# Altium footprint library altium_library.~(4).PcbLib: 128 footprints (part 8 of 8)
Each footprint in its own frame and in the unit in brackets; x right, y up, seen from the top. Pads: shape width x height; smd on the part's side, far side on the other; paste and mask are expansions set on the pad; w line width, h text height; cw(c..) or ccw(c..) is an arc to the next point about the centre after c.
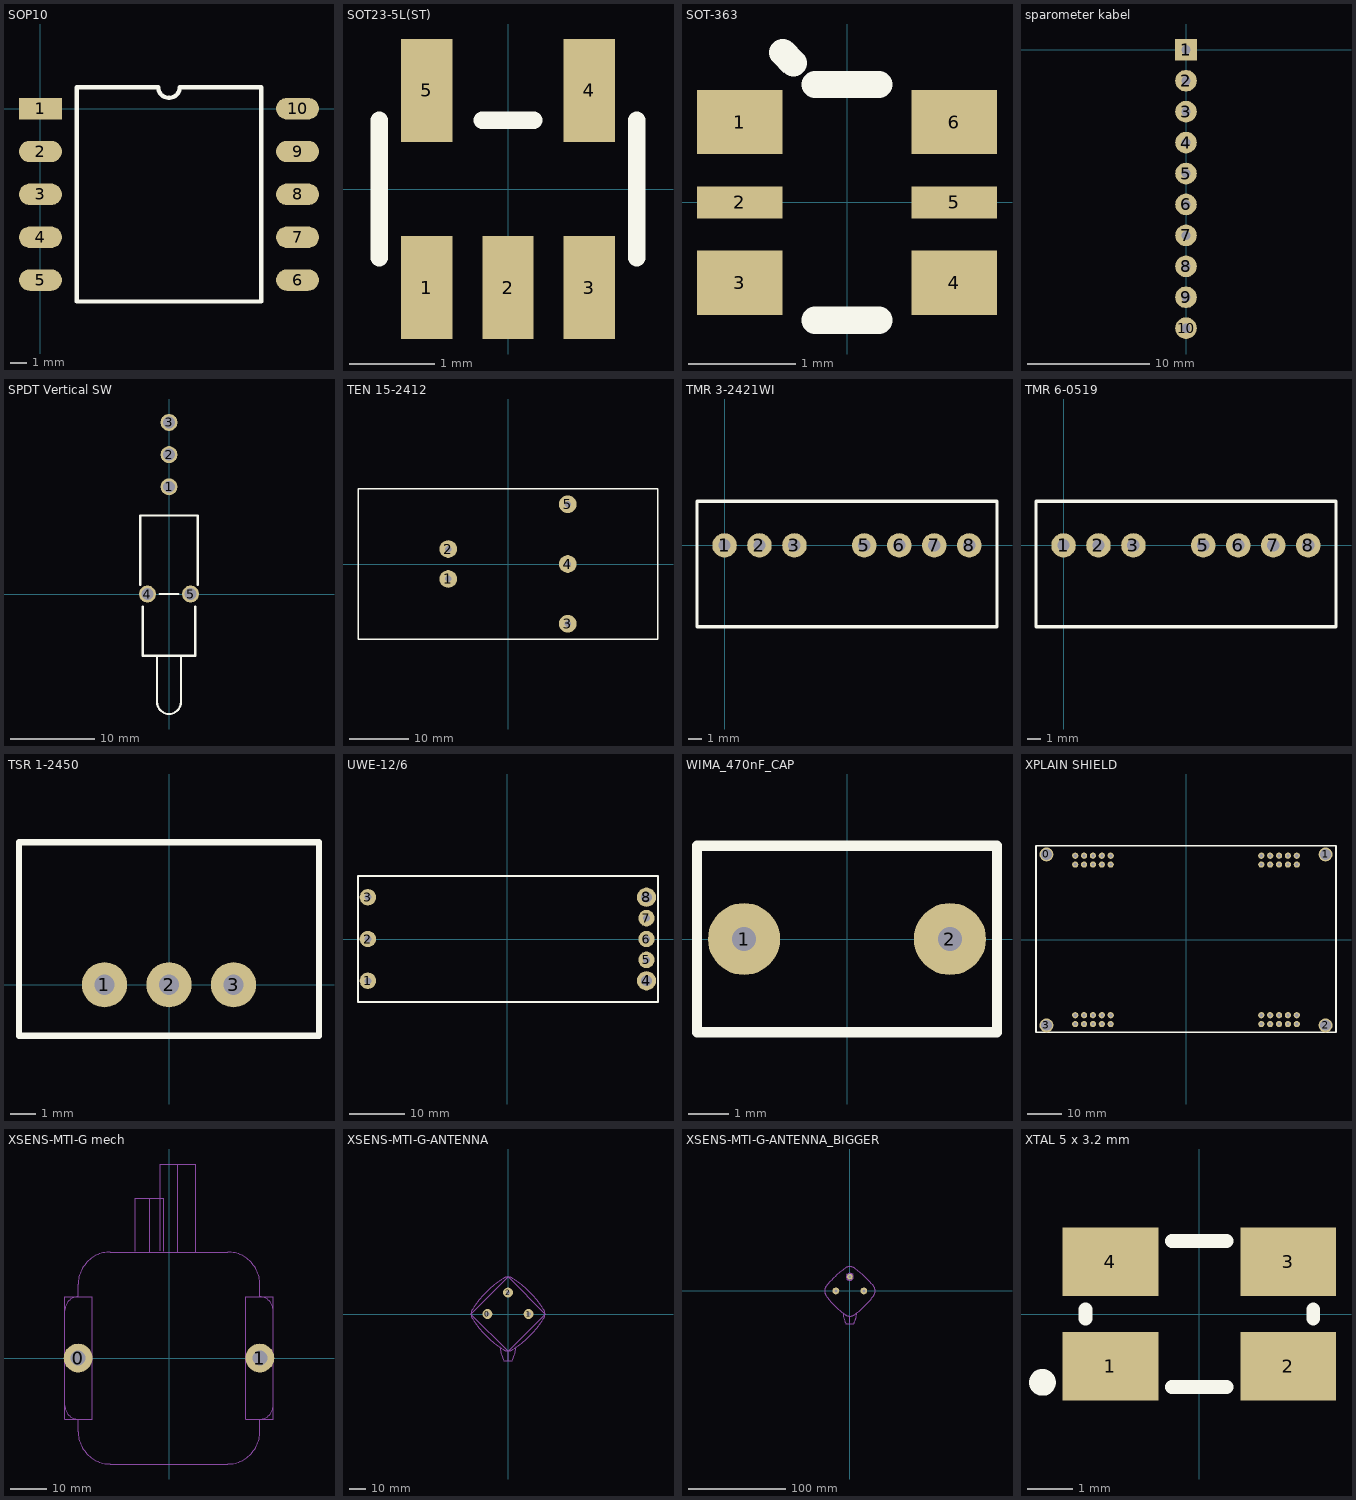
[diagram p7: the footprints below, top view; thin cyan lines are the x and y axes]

## SOP10 [mil]
pads (10):
  rect 100x50 smd: 1(0,0)
  oval 100x50 smd: 2(0,-100) 3(0,-200) 4(0,-300) 5(0,-400) 6(600,-400) 7(600,-300) 8(600,-200) 9(600,-100) 10(600,0)
Top Overlay:
  lines w10: 85,-450 515,-450 515,50 325,50 cw(c300,50) 275,50 85,50 85,-450

## SOT23-5L(ST) [mm]
pads (5):
  rect 0.6x1.2 smd: 1(-0.95,-1.15) 2(0,-1.15) 3(0.95,-1.15) 4(0.95,1.15) 5(-0.95,1.15)
Top Overlay:
  lines w0.203: -1.5,-0.8 -1.5,0.8 ; -0.3,0.8 0.3,0.8 ; 1.5,-0.8 1.5,0.8

## SOT-363 [mm]
pads (6):
  rect 0.8x0.6 smd: 1(-1,0.75) 3(-1,-0.75) 4(1,-0.75) 6(1,0.75)
  rect 0.8x0.3 smd: 2(-1,0) 5(1,0)
Top Overlay:
  lines w0.254: -0.6,1.4 -0.5,1.3 ; -0.3,-1.1 0.3,-1.1 ; -0.3,1.1 0.3,1.1

## sparometer kabel [mil]
pads (10):
  rect 70x70 hole 30: 1(0,0)
  round 70 hole 30: 2(0,-100) 3(0,-200) 4(0,-300) 5(0,-400) 6(0,-500) 7(0,-600) 8(0,-700) 9(0,-800) 10(0,-900)

## SPDT Vertical SW [mm] "T80-T Salecom"
pads (5):
  round 2 hole 1.4: 1(0,12.7) 2(0,16.51) 3(0,20.32) 4(-2.55,0) 5(2.55,0)
Top Overlay:
  lines w0.254: -3.4,1.1 -3.4,9.3 3.4,9.3 3.4,1.1 ; -3.1,-1.5 -3.1,-7.3 3.1,-7.3 3.1,-1.5 ; -1.4,-7.3 -1.4,-12.8 ccw(c0,-12.8) 1.4,-12.8 1.4,-7.3 ; -1.1,0 1.1,0

## TEN 15-2412 [mm]
pads (5):
  round 3 hole 1.1: 1(-10.16,-2.54) 2(-10.16,2.54) 3(10.16,-10.16) 4(10.16,0) 5(10.16,10.16)
Top Overlay:
  lines w0.254: 19.5,12.8 25.5,12.8 25.5,-12.8 -25.5,-12.8 -25.5,12.8 1.2,12.8 20.6,12.8

## TMR 3-2421WI [mil] "+-5v DC-DC converter 3W"
pads (7):
  round 70 hole 35.43: 1(0,0) 2(100,0) 3(200,0) 5(400,0) 6(500,0) 7(600,0) 8(700,0)
Top Overlay:
  lines w10: -78.74,-232.28 -78.74,125.98 779.53,125.98 779.53,-232.28 -78.74,-232.28

## TMR 6-0519 [mil] "9V DC-DC converter 6W"
pads (7):
  round 70 hole 35.43: 1(0,0) 2(100,0) 3(200,0) 5(400,0) 6(500,0) 7(600,0) 8(700,0)
Top Overlay:
  lines w10: -78.74,-232.28 -78.74,125.98 779.53,125.98 779.53,-232.28 -78.74,-232.28

## TSR 1-2450 [mil] "5V regulator"
pads (3):
  round 70 hole 31.5: 1(-100,0) 2(0,0) 3(100,0)
Top Overlay:
  lines w10: -232.28,-78.74 -232.28,220.47 232.28,220.47 232.28,-78.74 -232.28,-78.74

## UWE-12/6 [mm] "12 til 12 V 6A DC DC converter"
pads (8):
  round 3 hole 1.27: 1(-25.4,-7.62) 2(-25.4,0) 3(-25.4,7.62) 5(25.4,-3.81) 6(25.4,0) 7(25.4,3.81)
  round 3.5 hole 1.93: 4(25.4,-7.62) 8(25.4,7.62)
Top Overlay:
  lines w0.305: -27.2,-11.5 -27.2,11.5 27.5,11.5 27.5,-11.5 -27.2,-11.5

## WIMA_470nF_CAP [mil]
pads (2):
  round 70 hole 23.62: 1(-100,0) 2(100,0)
Top Overlay:
  lines w10: -145.67,-90.55 145.67,-90.55 145.67,90.55 -145.67,90.55 -145.67,-90.55

## XPLAIN SHIELD [mil]
pads (44):
  round 157.48 hole 122.05: 0(-1574.8,964.57) 1(1574.8,964.57) 2(1574.8,-964.57) 3(-1574.8,-964.57)
  round 70 hole 35.43: 11(850,850) 12(850,950) 13(950,850) 14(950,950) 15(1050,850) 16(1050,950) 17(1150,850) 18(1150,950) 19(1250,850) 20(1250,950) 21(850,-950) 22(850,-850) 23(950,-950) 24(950,-850) 25(1050,-950) 26(1050,-850) 27(1150,-950) 28(1150,-850) 29(1250,-950) 30(1250,-850) 31(-1250,-950) 32(-1250,-850) 33(-1150,-950) 34(-1150,-850) 35(-1050,-950) 36(-1050,-850) 37(-950,-950) 38(-950,-850) 39(-850,-950) 40(-850,-850) 41(-1250,850) 42(-1250,950) 43(-1150,850) 44(-1150,950) 45(-1050,850) 46(-1050,950) 47(-950,850) 48(-950,950) 49(-850,850) 50(-850,950)
Top Overlay:
  lines w20: -1692.91,-1043.31 -1692.91,1062.99 1692.91,1062.99 1692.91,-1043.31 -1692.91,-1043.31

## XSENS-MTI-G mech [mm]
pads (2):
  round 8 hole 4.2: 0(-25.3,0) 1(25.3,0)
Mechanical 1:
  lines w0.254: -29,-2.2 -29,-13.3 ccw(c-25.3,-13.3) -25.3,-17 -25.3,-20.5 ccw(c-16.3,-20.5) -16.3,-29.5 16.3,-29.5 ccw(c16.3,-20.5) 25.3,-20.5 25.3,-17 ccw(c25.3,-13.3) 29,-13.3 29,-2.7 ; -29,2.8 -29,13.3 cw(c-25.3,13.3) -25.3,17 -25.3,20.5 cw(c-16.3,20.5) -16.3,29.5 16.3,29.5 cw(c16.3,20.5) 25.3,20.5 25.3,17.1 ; -9.4,29.7 -9.4,44.5 -5.4,44.5 ; -5.4,29.5 -5.4,44.5 ; -2.5,29.8 -2.5,44.6 -2.5,54 2.5,54 ; -1.4,29.7 -1.4,44.5 -5.4,44.5 ; 2.5,29.5 2.5,54 ; 7.5,29.6 7.5,54 2.5,54 ; 25.3,17 cw(c25.3,13.3) 29,13.3 29,2.6 ; -29,-17 -29,17 -21.4,17 -21.4,-17 -29,-17 ; 21.4,-17 29,-17 29,17 21.4,17 21.4,-17

## XSENS-MTI-G-ANTENNA [mm]
pads (3):
  round 6 hole 2.7: 0(-12.5,0) 1(12.5,0) 2(0,13)
Mechanical 1:
  lines w0.254: -5,-20 ccw(c26.386,-15.386) -2.5,-28.5 2.5,-28.5 ccw(c-26.386,-15.386) 5,-20 ; 0,-28.5 0,-22.5 ; 0,-22.5 -22.5,0 0,22.5 22.5,0 0,-22.5 ; -21.5,-3 ccw(c30,30) -3,-21.5 ccw(c0,-17.5) 3,-21.5 ccw(c-30,30) 21.5,-3 ccw(c17.5,0) 21.5,3 ccw(c-30,-30) 3,21.5 ccw(c0,17.5) -3,21.5 ccw(c30,-30) -21.5,3 ccw(c-17.5,0) -21.5,-3

## XSENS-MTI-G-ANTENNA_BIGGER [mm]
pads (3):
  round 7 hole 3: 0(-14.4,0) 1(14.4,0)
  round 6 hole 2.7: 2(0,14.5)
Mechanical 1:
  circle w0.254: c0,14.5 r3.536
  lines w0.254: -7,-23 ccw(c19.643,-21.643) -4,-34 4,-34 ccw(c-19.643,-21.643) 7,-23 ; -3.041,17.065 cw(c-14.4,0) 2.704,11.3 ; -2.97,10.888 cw(c14.4,0) 3.562,17.401 ; 0,-32 0,-26 ; -24.4,-4.8 ccw(c38.166,38.166) -4.8,-24.4 ccw(c0,-18) 4.8,-24.4 ccw(c-38.166,38.166) 24.4,-4.8 ccw(c18,0) 24.4,4.8 ccw(c-55.134,-59.384) 4.8,23.4 ccw(c0,17) -4.8,23.4 ccw(c52.725,-56.844) -24.4,4.8 ccw(c-18,0) -24.4,-4.8

## XTAL 5 x 3.2 mm [mm]
pads (4):
  rect 2.1x1.5 smd: 1(-1.95,-1.15) 2(1.95,-1.15) 3(1.95,1.15) 4(-1.95,1.15)
Top Overlay:
  circle w0.305: c-3.441,-1.5 r0.141
  lines w0.305: -2.5,-0.1 -2.5,0.1 ; -0.6,-1.6 0.6,-1.6 ; -0.6,1.6 0.6,1.6 ; 2.5,-0.1 2.5,0.1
